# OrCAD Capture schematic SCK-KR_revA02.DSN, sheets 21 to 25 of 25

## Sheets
21 21_PL_GEM3: size Custom
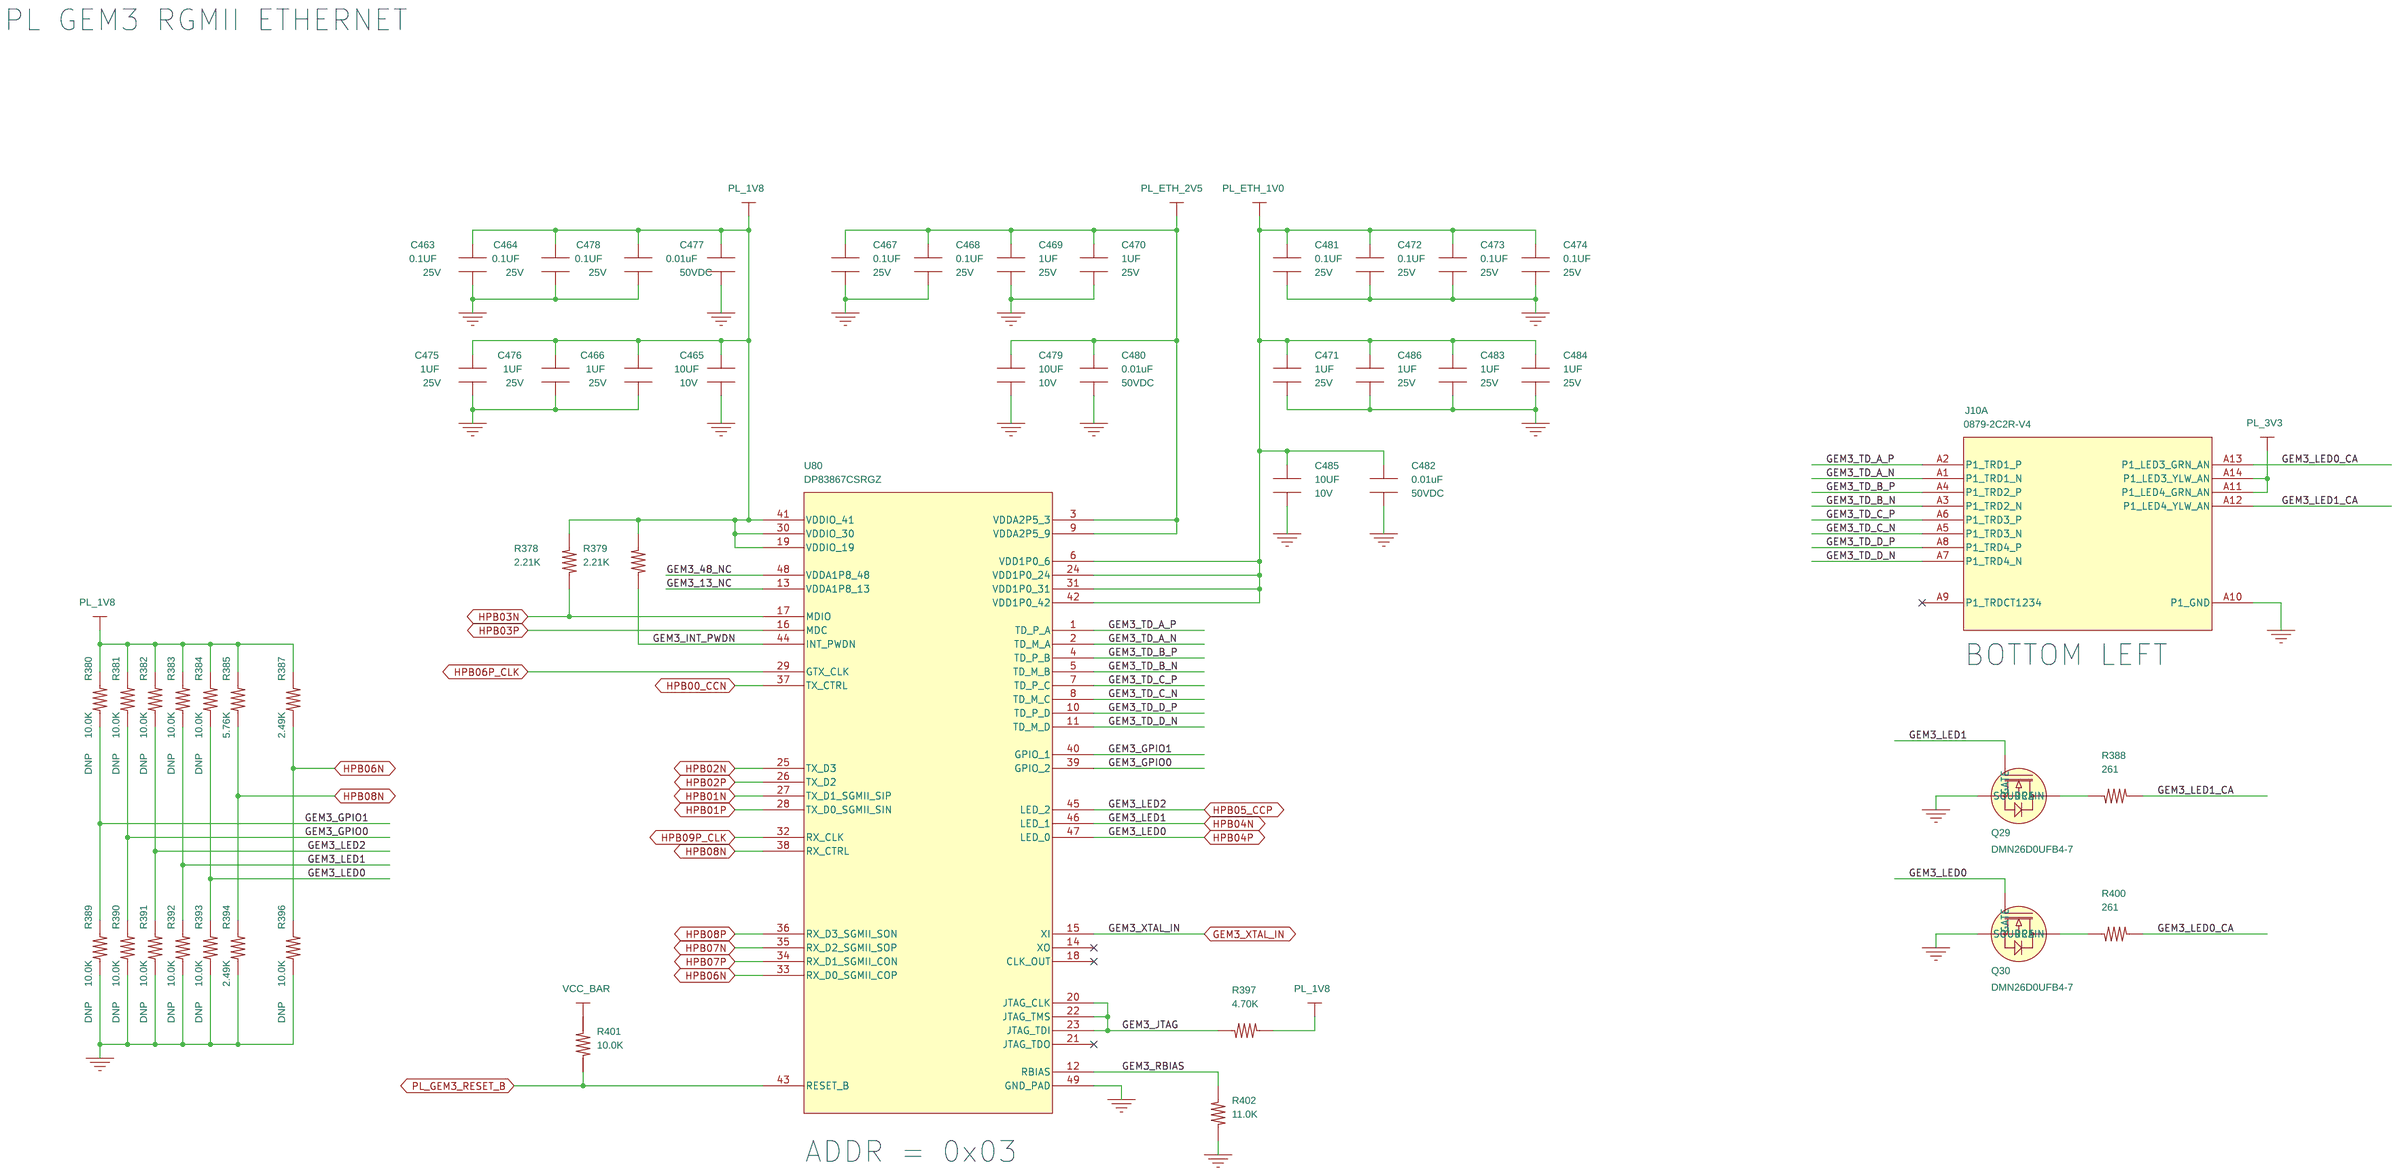
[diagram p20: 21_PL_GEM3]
22 22_SD Card: size Custom
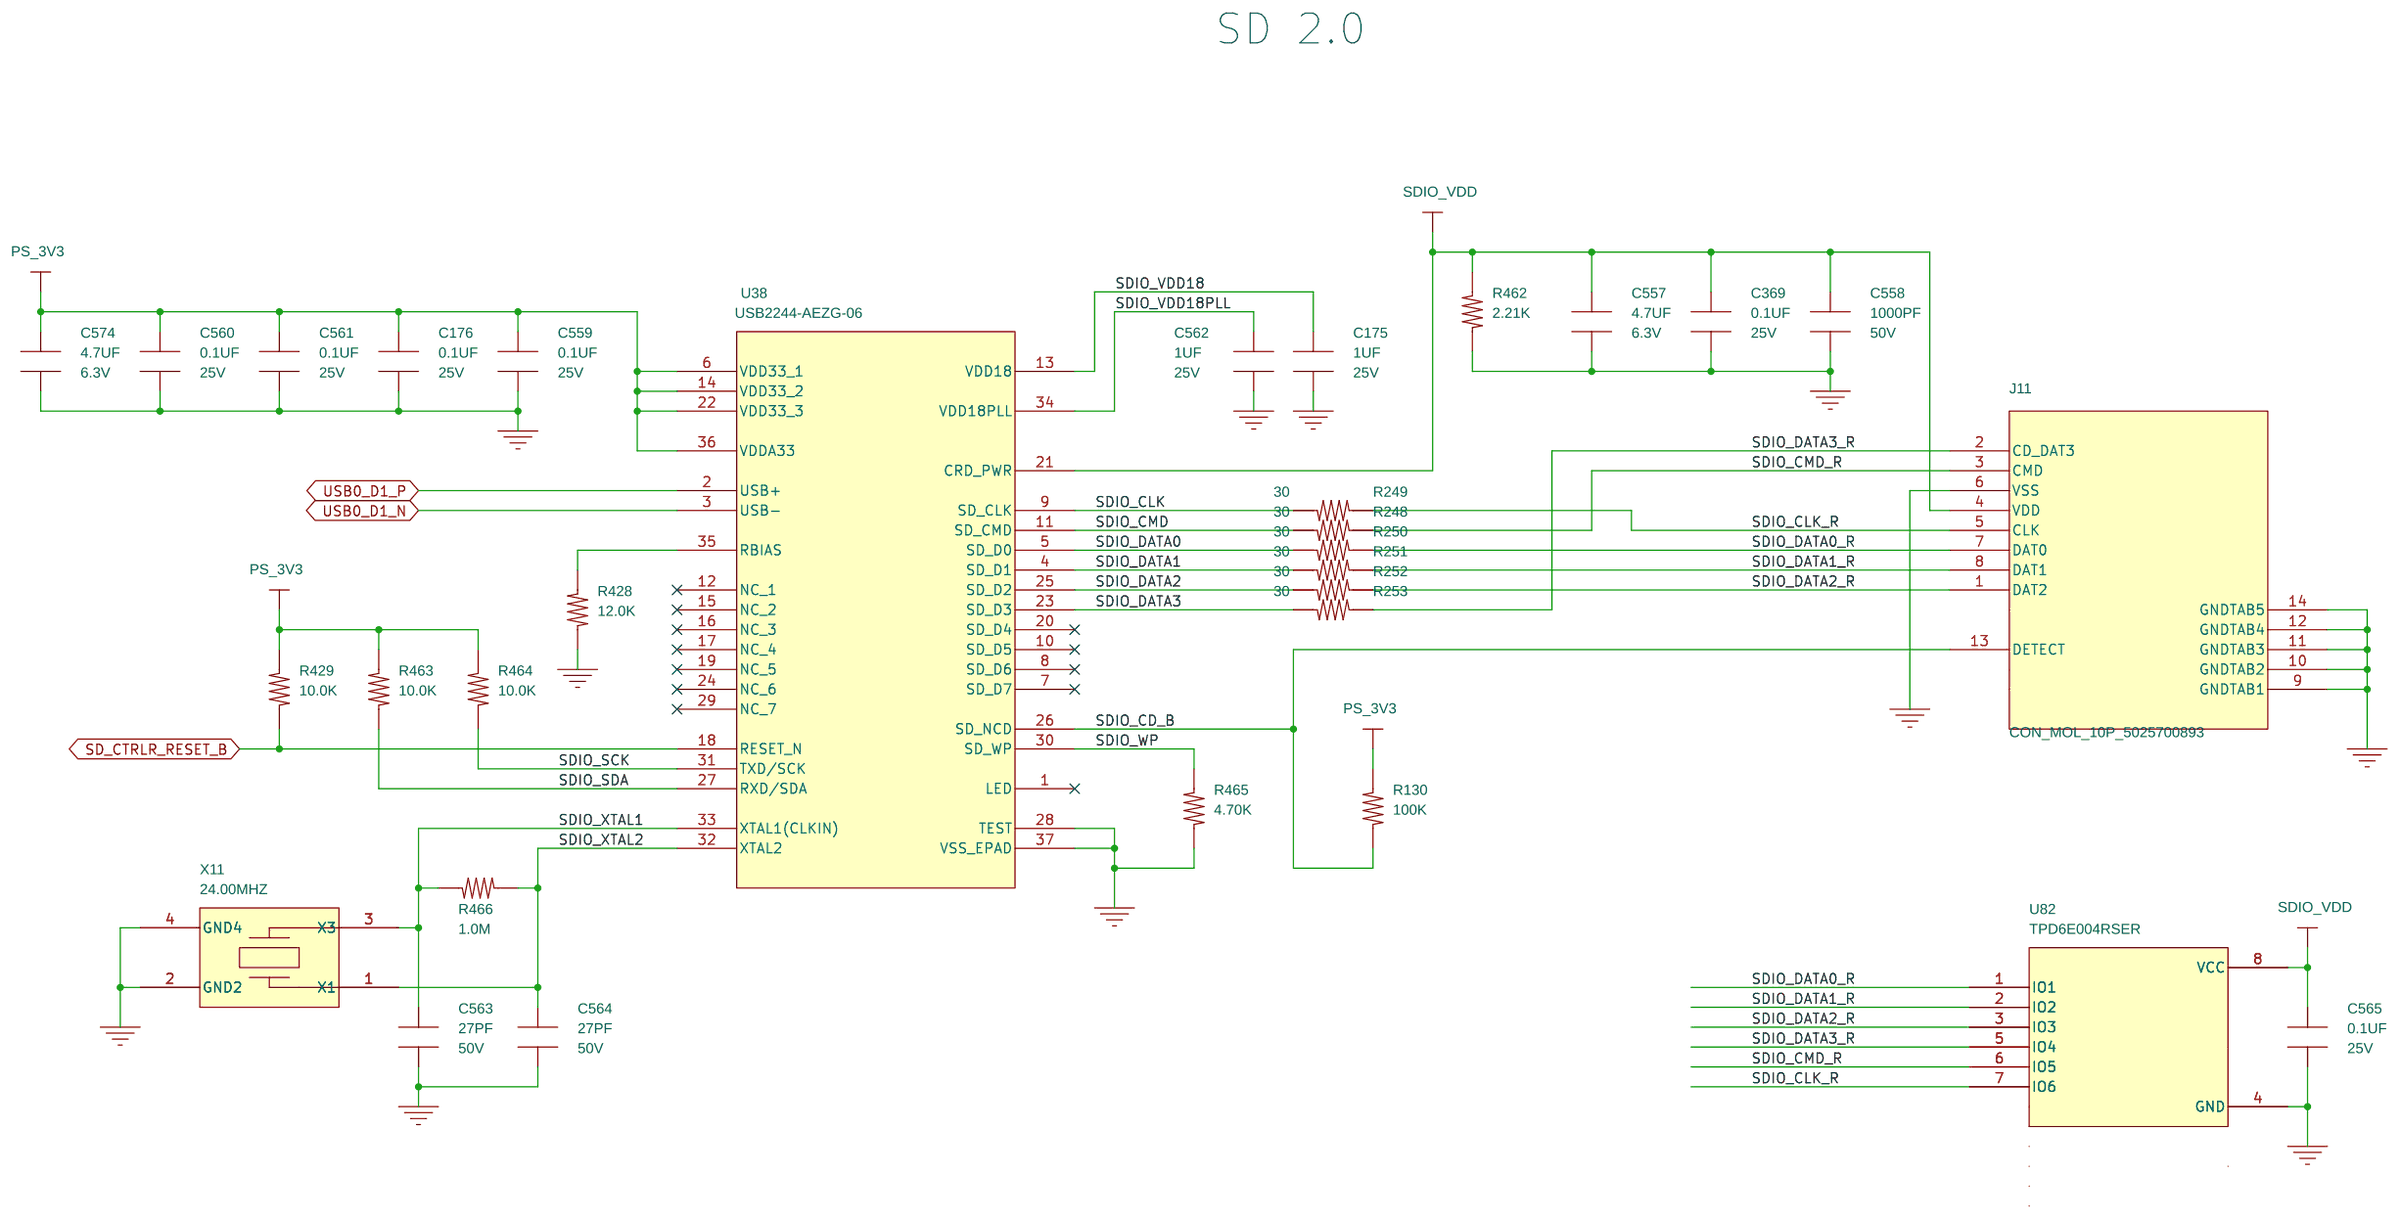
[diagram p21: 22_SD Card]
23 23_USB Connectors: size Custom
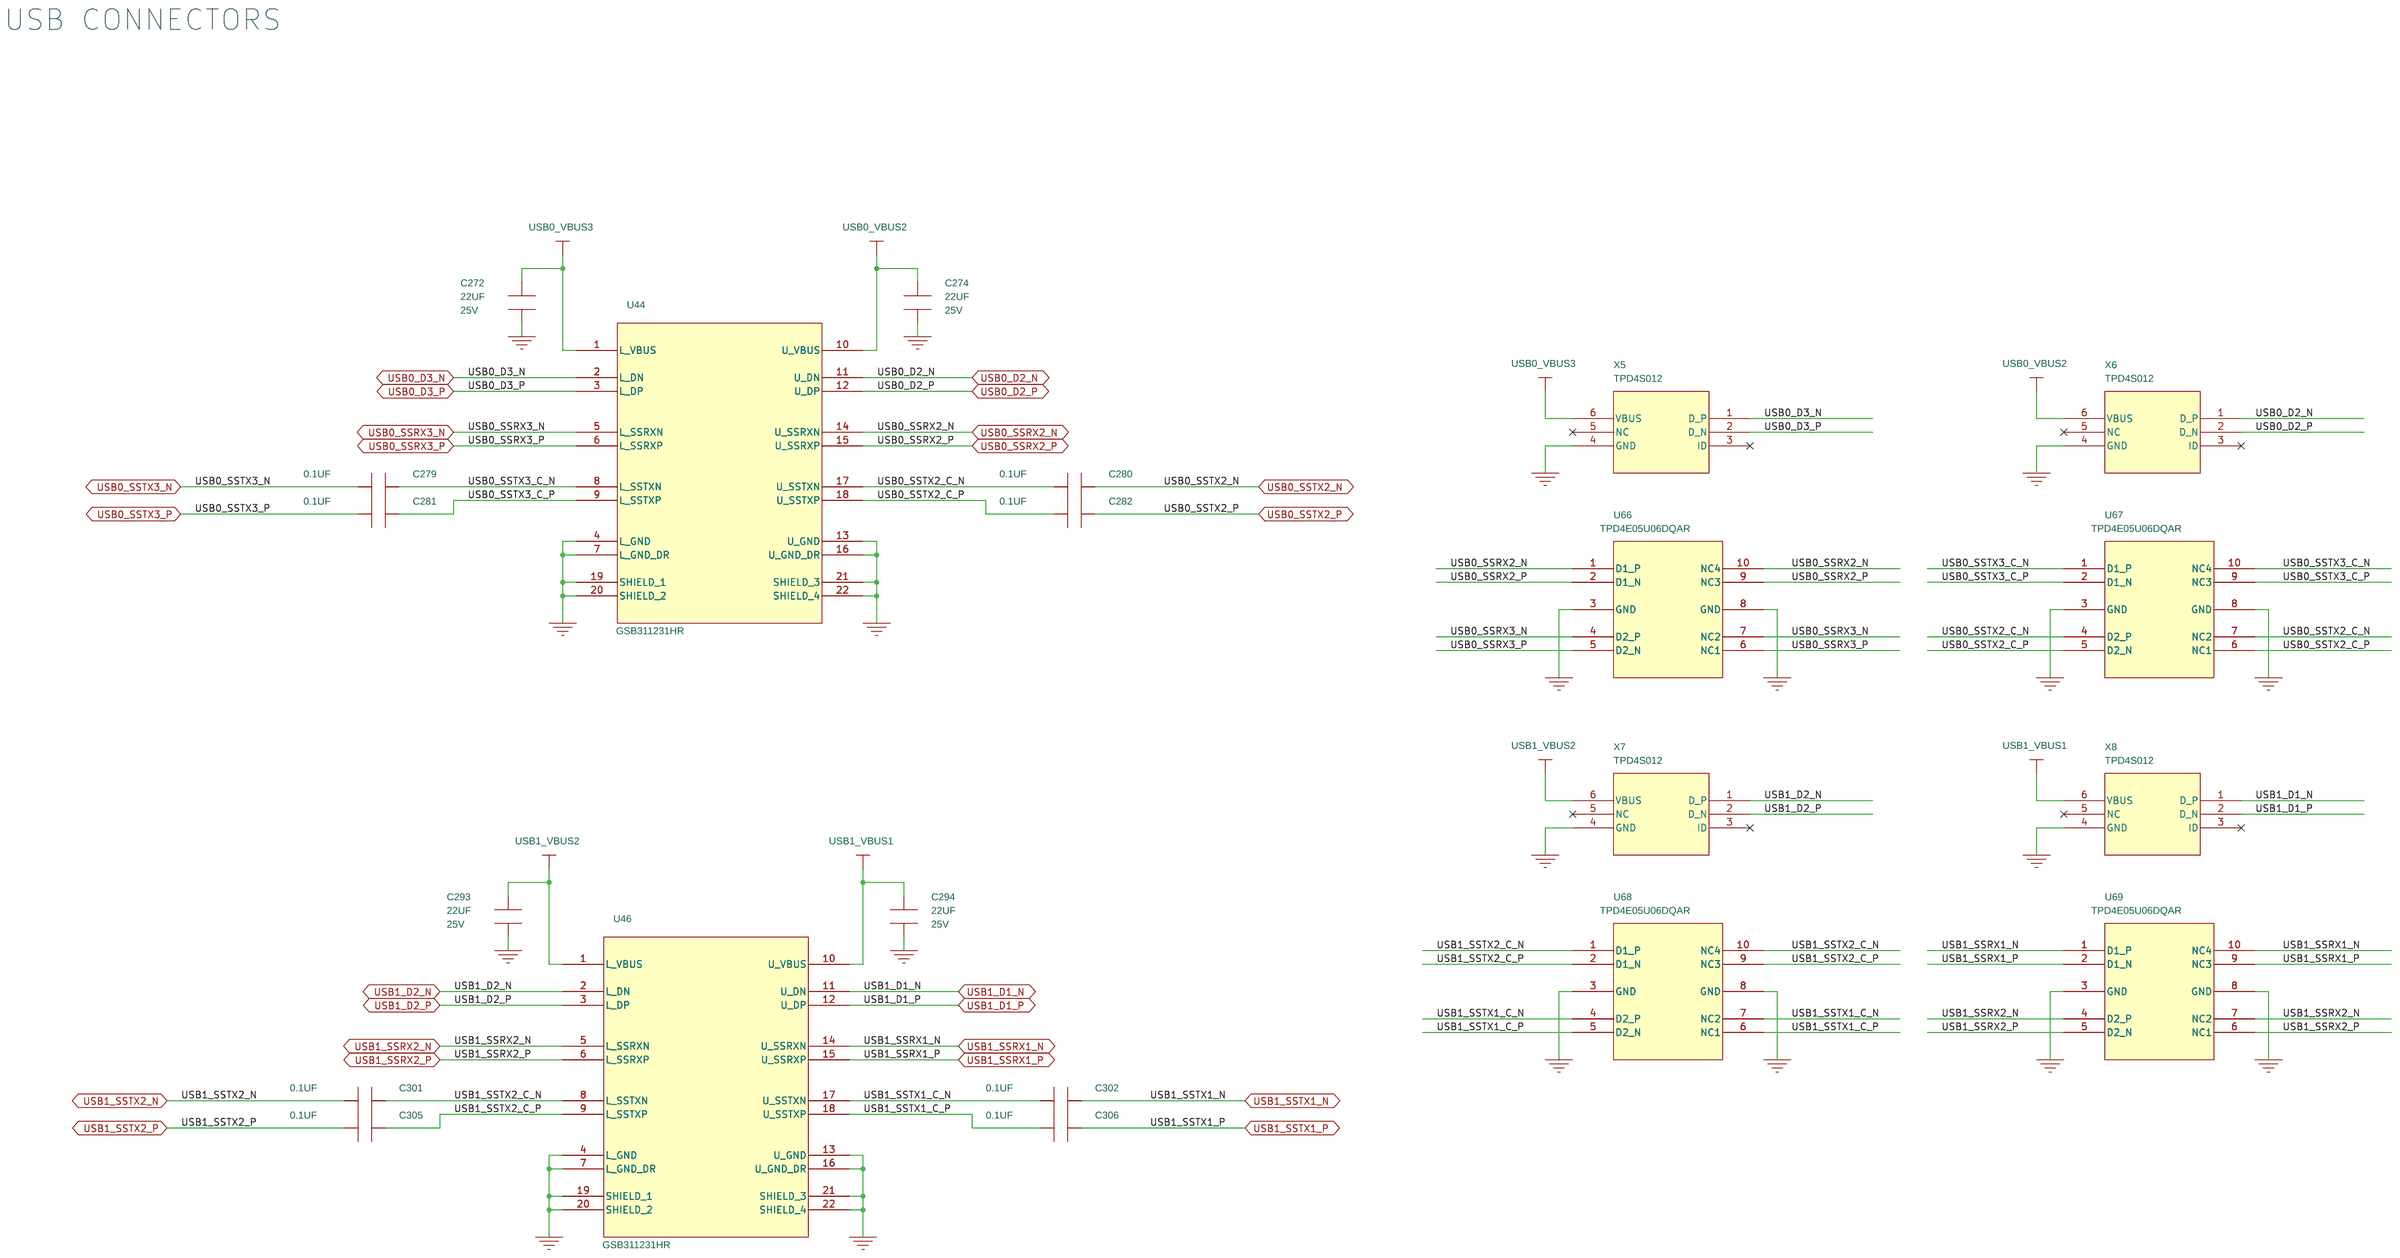
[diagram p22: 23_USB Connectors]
24 24_USB0 PHY and Hub: size Custom
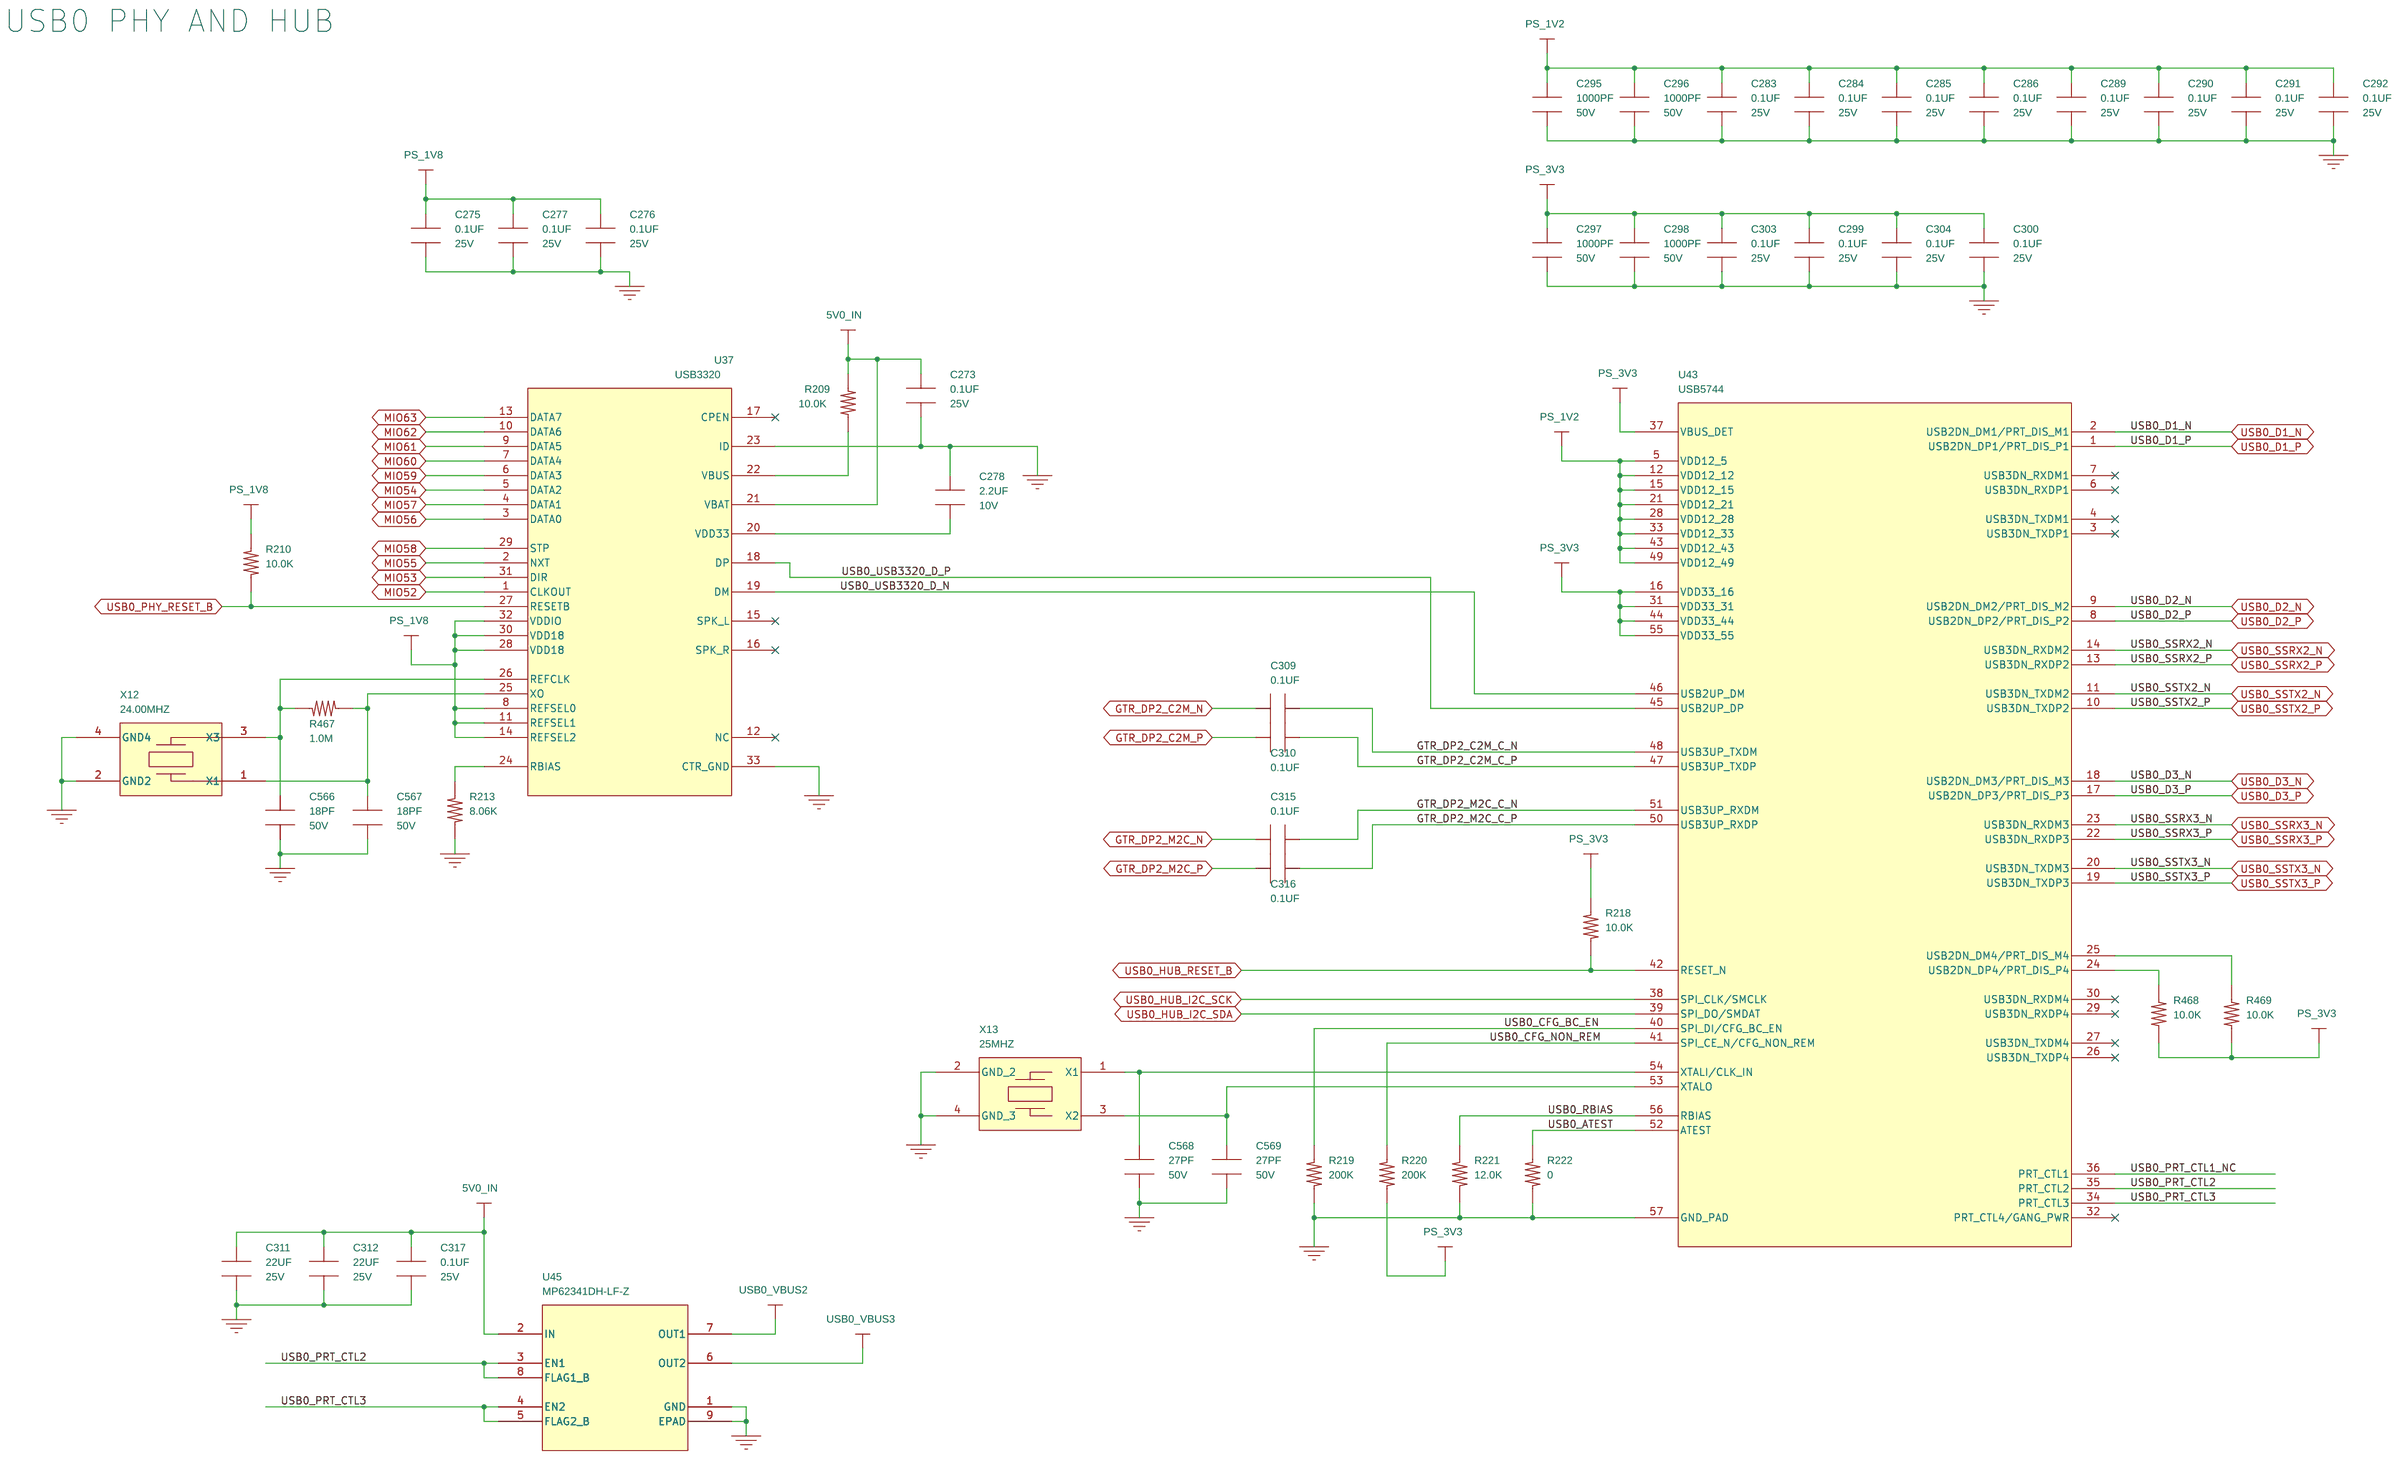
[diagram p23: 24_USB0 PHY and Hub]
25 25_USB1 PHY and Hub: size Custom
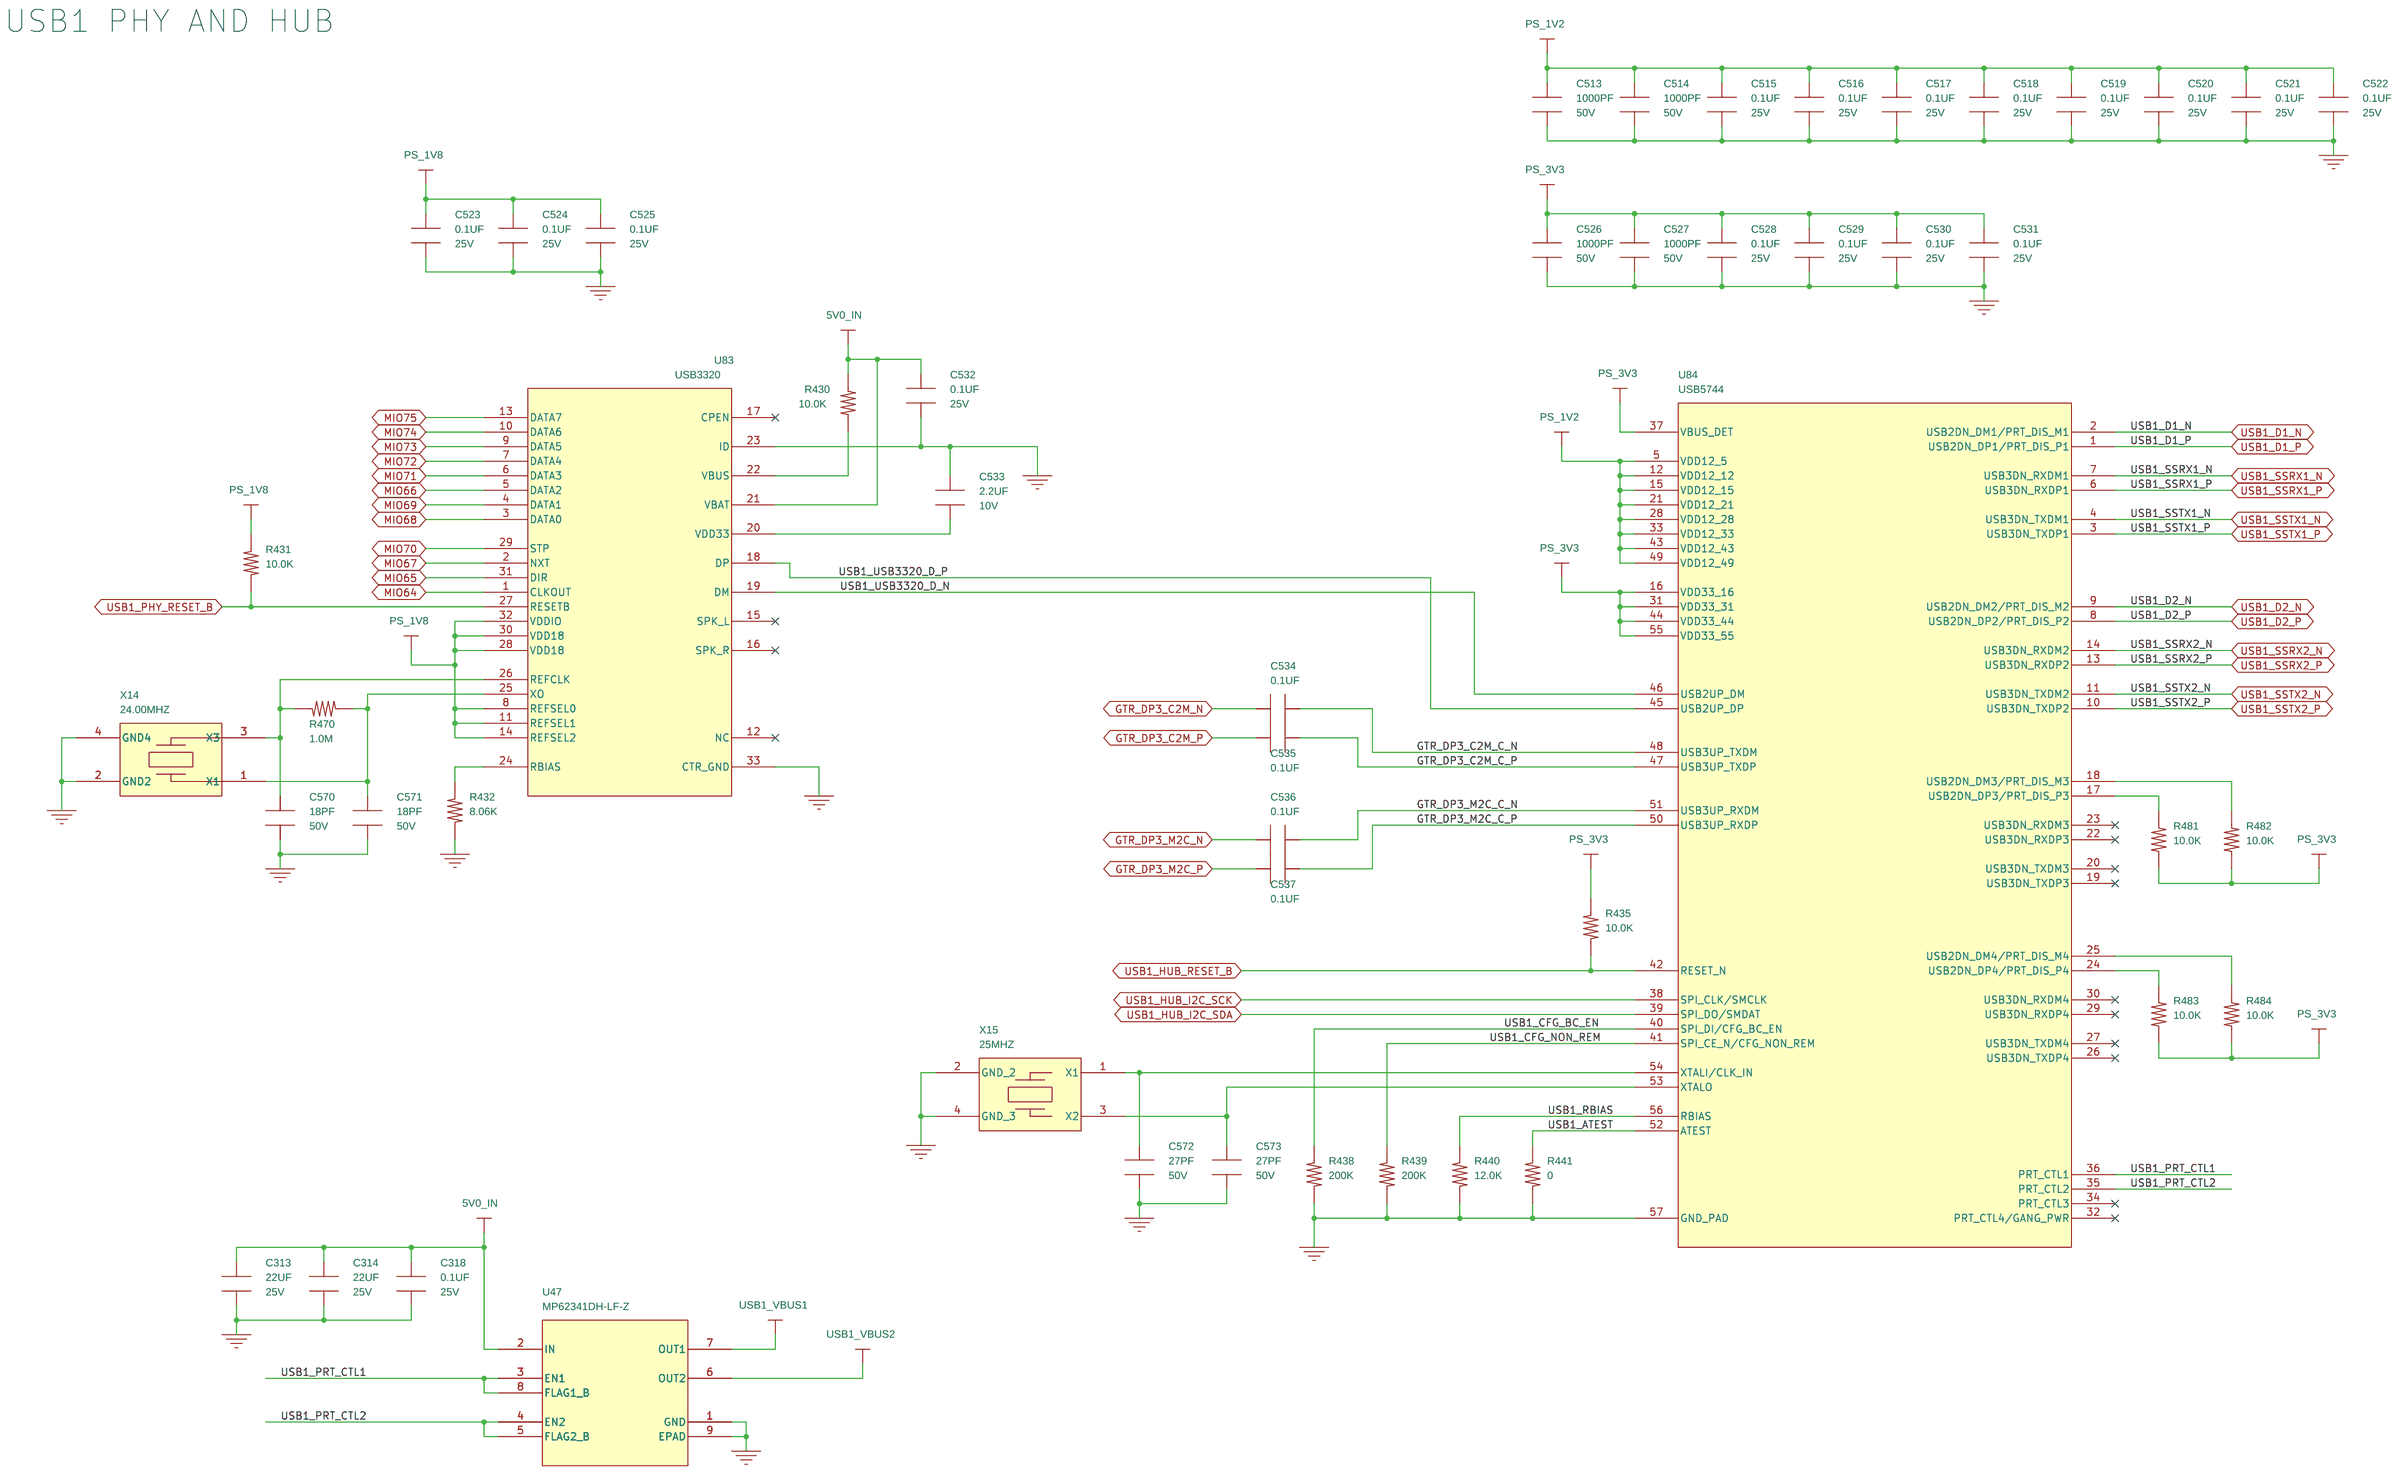
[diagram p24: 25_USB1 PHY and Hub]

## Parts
sheet 18_PS_GEM0
J10  0879-2C2R-V4  [CON_BEL_0879_2C2R_V4]  (sections A,B,C,D)
sheet 21_PL_GEM3
C463  0.1UF  [CAPC100X50X55]
C464  0.1UF  [CAPC100X50X55]
C465  10UF  [CAPC100X50X70]
C466  1UF  [CAPC100X50X70]
C467  0.1UF  [CAPC100X50X55]
C468  0.1UF  [CAPC100X50X55]
C469  1UF  [CAPC100X50X70]
C470  1UF  [CAPC100X50X70]
C471  1UF  [CAPC100X50X70]
C472  0.1UF  [CAPC100X50X55]
C473  0.1UF  [CAPC100X50X55]
C474  0.1UF  [CAPC100X50X55]
C475  1UF  [CAPC100X50X70]
C476  1UF  [CAPC100X50X70]
C477  0.01uF  [CAPC100X50X55]
C478  0.1UF  [CAPC100X50X55]
C479  10UF  [CAPC100X50X70]
C480  0.01uF  [CAPC100X50X55]
C481  0.1UF  [CAPC100X50X55]
C482  0.01uF  [CAPC100X50X55]
C483  1UF  [CAPC100X50X70]
C484  1UF  [CAPC100X50X70]
C485  10UF  [CAPC100X50X70]
C486  1UF  [CAPC100X50X70]
Q29  DMN26D0UFB4-7  [DFN_105X65x40_3]
Q30  DMN26D0UFB4-7  [DFN_105X65x40_3]
R378  2.21K  [RESC100X50X40]
R379  2.21K  [RESC100X50X40]
R380  10.0K  [RESC100X50X40]
R381  10.0K  [RESC100X50X40]
R382  10.0K  [RESC100X50X40]
R383  10.0K  [RESC100X50X40]
R384  10.0K  [RESC100X50X40]
R385  5.76K  [RESC100X50X40]
R387  2.49K  [RESC100X50X40]
R388  261  [RESC100X50X40]
R389  10.0K  [RESC100X50X40]
R390  10.0K  [RESC100X50X40]
R391  10.0K  [RESC100X50X40]
R392  10.0K  [RESC100X50X40]
R393  10.0K  [RESC100X50X40]
R394  2.49K  [RESC100X50X40]
R396  10.0K  [RESC100X50X40]
R397  4.70K  [RESC100X50X40]
R400  261  [RESC100X50X40]
R401  10.0K  [RESC100X50X40]
R402  11.0K  [RESC100X50X40]
U80  DP83867CSRGZ  [VQFN05P700X700X100_48_408EP]
sheet 22_SD Card
C175  1UF  [CAPC100X50X70]
C176  0.1UF  [CAPC100X50X55]
C369  0.1UF  [CAPC100X50X55]
C557  4.7UF  [CAPC100X50X60]
C558  1000PF  [CAPC100X50X55]
C559  0.1UF  [CAPC100X50X55]
C560  0.1UF  [CAPC100X50X55]
C561  0.1UF  [CAPC100X50X55]
C562  1UF  [CAPC100X50X70]
C563  27PF  [CAPC100X50X55]
C564  27PF  [CAPC100X50X55]
C565  0.1UF  [CAPC100X50X55]
C574  4.7UF  [CAPC100X50X60]
J11  CON_MOL_10P_5025700893  [CON_MOL_10P_5025700893]
R130  100K  [RESC100X50X40]
R248  30  [RESC100X50X40]
R249  30  [RESC100X50X40]
R250  30  [RESC100X50X40]
R251  30  [RESC100X50X40]
R252  30  [RESC100X50X40]
R253  30  [RESC100X50X40]
R428  12.0K  [RESC100X50X40]
R429  10.0K  [RESC100X50X40]
R462  2.21K  [RESC100X50X40]
R463  10.0K  [RESC100X50X40]
R464  10.0K  [RESC100X50X40]
R465  4.70K  [RESC100X50X40]
R466  1.0M  [RESC100X50X40]
U38  USB2244-AEZG-06  [QFN05P600X600X85-36_410]
U82  TPD6E004RSER  [uqfn_8]
X11  24.00MHZ  [XTAL_EPSON_FA238]
sheet 23_USB Connectors
C272  22UF  [CAPC200X125X145]
C274  22UF  [CAPC200X125X145]
C279  0.1UF  [CAPC100X50X55]
C280  0.1UF  [CAPC100X50X55]
C281  0.1UF  [CAPC100X50X55]
C282  0.1UF  [CAPC100X50X55]
C293  22UF  [CAPC200X125X145]
C294  22UF  [CAPC200X125X145]
C301  0.1UF  [CAPC100X50X55]
C302  0.1UF  [CAPC100X50X55]
C305  0.1UF  [CAPC100X50X55]
C306  0.1UF  [CAPC100X50X55]
U44  GSB311231HR  [CONN_USB_DUAL_GSB311231HR]
U46  GSB311231HR  [CONN_USB_DUAL_GSB311231HR]
U66  TPD4E05U06DQAR  [DQA_R_PSON_N10]
U67  TPD4E05U06DQAR  [DQA_R_PSON_N10]
U68  TPD4E05U06DQAR  [DQA_R_PSON_N10]
U69  TPD4E05U06DQAR  [DQA_R_PSON_N10]
X5  TPD4S012  [DRY_6_SON]
X6  TPD4S012  [DRY_6_SON]
X7  TPD4S012  [DRY_6_SON]
X8  TPD4S012  [DRY_6_SON]
sheet 24_USB0 PHY and Hub
C273  0.1UF  [CAPC100X50X55]
C275  0.1UF  [CAPC100X50X55]
C276  0.1UF  [CAPC100X50X55]
C277  0.1UF  [CAPC100X50X55]
C278  2.2UF  [CAPC100X50X55]
C283  0.1UF  [CAPC100X50X55]
C284  0.1UF  [CAPC100X50X55]
C285  0.1UF  [CAPC100X50X55]
C286  0.1UF  [CAPC100X50X55]
C289  0.1UF  [CAPC100X50X55]
C290  0.1UF  [CAPC100X50X55]
C291  0.1UF  [CAPC100X50X55]
C292  0.1UF  [CAPC100X50X55]
C295  1000PF  [CAPC100X50X55]
C296  1000PF  [CAPC100X50X55]
C297  1000PF  [CAPC100X50X55]
C298  1000PF  [CAPC100X50X55]
C299  0.1UF  [CAPC100X50X55]
C300  0.1UF  [CAPC100X50X55]
C303  0.1UF  [CAPC100X50X55]
C304  0.1UF  [CAPC100X50X55]
C309  0.1UF  [CAPC100X50X55]
C310  0.1UF  [CAPC100X50X55]
C311  22UF  [CAPC200X125X145]
C312  22UF  [CAPC200X125X145]
C315  0.1UF  [CAPC100X50X55]
C316  0.1UF  [CAPC100X50X55]
C317  0.1UF  [CAPC100X50X55]
C566  18PF  [CAPC100X50X50]
C567  18PF  [CAPC100X50X50]
C568  27PF  [CAPC100X50X55]
C569  27PF  [CAPC100X50X55]
R209  10.0K  [RESC100X50X40]
R210  10.0K  [RESC100X50X40]
R213  8.06K  [RESC100X50X40]
R218  10.0K  [RESC100X50X40]
R219  200K  [RESC100X50X40]
R220  200K  [RESC100X50X40]
R221  12.0K  [RESC100X50X40]
R222  0  [RESC100X50X40]
R467  1.0M  [RESC100X50X40]
R468  10.0K  [RESC100X50X40]
R469  10.0K  [RESC100X50X40]
U37  USB3320  [QFN05P500X500X100_32P_330EP]
U43  USB5744  [VQFN40P700X700X100-56_460EP]
U45  MP62341DH-LF-Z  [MSOP8E65P490X110]
X12  24.00MHZ  [XTAL_EPSON_FA238]
X13  25MHZ  [XTAL_EPSON_FA238]
sheet 25_USB1 PHY and Hub
C313  22UF  [CAPC200X125X145]
C314  22UF  [CAPC200X125X145]
C318  0.1UF  [CAPC100X50X55]
C513  1000PF  [CAPC100X50X55]
C514  1000PF  [CAPC100X50X55]
C515  0.1UF  [CAPC100X50X55]
C516  0.1UF  [CAPC100X50X55]
C517  0.1UF  [CAPC100X50X55]
C518  0.1UF  [CAPC100X50X55]
C519  0.1UF  [CAPC100X50X55]
C520  0.1UF  [CAPC100X50X55]
C521  0.1UF  [CAPC100X50X55]
C522  0.1UF  [CAPC100X50X55]
C523  0.1UF  [CAPC100X50X55]
C524  0.1UF  [CAPC100X50X55]
C525  0.1UF  [CAPC100X50X55]
C526  1000PF  [CAPC100X50X55]
C527  1000PF  [CAPC100X50X55]
C528  0.1UF  [CAPC100X50X55]
C529  0.1UF  [CAPC100X50X55]
C530  0.1UF  [CAPC100X50X55]
C531  0.1UF  [CAPC100X50X55]
C532  0.1UF  [CAPC100X50X55]
C533  2.2UF  [CAPC100X50X55]
C534  0.1UF  [CAPC100X50X55]
C535  0.1UF  [CAPC100X50X55]
C536  0.1UF  [CAPC100X50X55]
C537  0.1UF  [CAPC100X50X55]
C570  18PF  [CAPC100X50X50]
C571  18PF  [CAPC100X50X50]
C572  27PF  [CAPC100X50X55]
C573  27PF  [CAPC100X50X55]
R430  10.0K  [RESC100X50X40]
R431  10.0K  [RESC100X50X40]
R432  8.06K  [RESC100X50X40]
R435  10.0K  [RESC100X50X40]
R438  200K  [RESC100X50X40]
R439  200K  [RESC100X50X40]
R440  12.0K  [RESC100X50X40]
R441  0  [RESC100X50X40]
R470  1.0M  [RESC100X50X40]
R481  10.0K  [RESC100X50X40]
R482  10.0K  [RESC100X50X40]
R483  10.0K  [RESC100X50X40]
R484  10.0K  [RESC100X50X40]
U47  MP62341DH-LF-Z  [MSOP8E65P490X110]
U83  USB3320  [QFN05P500X500X100_32P_330EP]
U84  USB5744  [VQFN40P700X700X100-56_460EP]
X14  24.00MHZ  [XTAL_EPSON_FA238]
X15  25MHZ  [XTAL_EPSON_FA238]

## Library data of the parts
J10 = RJ45_0879-2C2R-V4: Conn Rcpt RJ-45 1000Base-T RA  Quad 2x2 1.27mm P TH 4-LED Y/G Magnetics; Agile Part Number: CON-00474-01; Barcode: 40000147; CIP Link: http://xsjbrdwin1/CIP-E/Component/Index/All?pn=40000147; Part Type: Unassigned Part Type
C176 C273 C275-C277 C279-C286 C289-C292 C299-C306 C309 C310 C315-C318 C369 C463 C464 C467 C468 C472-C474 C478 C481 C515-C525 C528-C532 C534-C537 C559-C561 C565 = CAP_NP: Cap Cer 100nF 10% 25V X5R 0402; ALT_SYMBOLS: CAPC100X50X55RND; Agile Part Number: CAP-00068-01; CIP Link: http://xsjbrdwin1/CIP-E/Component/Index/All?pn=100040; Dielectric Type: X5R; Manufacturer: TAIYO YUDEN; Manufacturer PN: TMK105BJ104KV-F; OWNER: 4001; PRICE: 0.01; Part Type: CERAMIC; PartType: CERAMIC; ROHS: Yes; Tolerance: 10%; Voltage: 25V; barcode: 100040
C465 C479 C485 = CAP_NP: Cap Cer 10uF 20% 10V X5R 0402; Agile Part Number: CAP-00170-01; CIP Link: http://xsjbrdwin1/CIP-E/Component/Index/All?pn=100197; Dielectric Type: X5R; Manufacturer: SAMSUNG; Manufacturer PN: CL05A106MP5NUNC; OWNER: 3709; PRICE: 0.09; Part Type: CERAMIC; PartType: CERAMIC; ROHS: Yes; Tolerance: 20%; Voltage: 10V; barcode: 100197
C175 C466 C469-C471 C475 C476 C483 C484 C486 C562 = CAP_NP: Cap Cer 1uF 10% 25V X6S 0402; ALT_SYMBOLS: CAPC100X50X55RND; Agile Part Number: CAP-00009-01; Barcode: 100269; CIP Link: http://xsjbrdwin1/CIP-E/Component/Index/All?pn=100269; Dielectric Type: X6S; Manufacturer: MURATA; Manufacturer PN: GRM155C81E105KE11D; Part Type: CERAMIC; Tolerance: 10%; Voltage: 25V
C477 C480 C482 = CAP_NP: Cap Cer 10nF 10% 50V X7R 0402; ALT_SYMBOLS: CAPC100X50X55RND; Agile Part Number: CAP-00031-01; CIP Link: http://xsjbrdwin1/CIP-E/Component/Index/All?pn=100003; Dielectric Type: X7R; Manufacturer: Yageo; Manufacturer PN: CC0402KRX7R9BB103; OWNER: 4001; PRICE: 0; Part Type: CERAMIC; PartType: CERAMIC; ROHS: Yes; Tolerance: 10%; Voltage: 50VDC; barcode: 100003; Datasheet: http://download.siliconexpert.com/pdfs/2017/7/31/11/40/26/700/yageo_/manual/1073881636569039upy-gphc_x7r_6.3v-to-50v_18.pdf
Q29 Q30 = DMN26D0UFB4: MOSFET N-CH 20V 230MA DFN; Agile Part Number: TRN-00054-01; Barcode: 83000008; CIP Link: http://xsjbrdwin1/CIP-E/Component/Index/All?pn=83000008; Manufacturer: Diodes Incorporated; Part Type: FET; Rated Power: 350mW (Ta); Datasheet: https://www.diodes.com/assets/Datasheets/ds31775.pdf
R378 R379 R462 = RES: Res 2K21 1% 1/16W 100PPM 50V 0402; ALT_SYMBOLS: (0402,C402-25,RESC100X50X40L25NRND); Agile Part Number: RES-00023-01; Barcode: 200163; CIP Link: http://xsjbrdwin1/CIP-E/Component/Index/All?pn=200163; Manufacturer: PANASONIC; Manufacturer PN: ERJ2RKF2211X; OWNER: 3709; PRICE: 0; Part Type: SMT - 1%; PartType: SMT - 1%; Power: 1/10W; ROHS: Yes; Rated Power: 1/16W; Tolerance: 1%; primarykey: 254
R380-R384 R389-R393 R396 = RES: Res 10K 1% 1/16W 100PPM 50V 0402; ALT_SYMBOLS: RESC100X50X40RND; ASSEMBLY_OPTIONS: DNP; Agile Part Number: RES-00030-01; Barcode: 200025; CIP Link: http://xsjbrdwin1/CIP-E/Component/Index/All?pn=200025; Manufacturer: PANASONIC; Manufacturer PN: ERJ2RKF1002X; OWNER: 3709; PRICE: 0; Part Type: SMT - 1%; PartType: SMT - DNP; Power: DNP; ROHS: Yes; Rated Power: 1/16W; Tolerance: 1%; primarykey: 73
R385 = RES: RES 5.76 KOHM 1% 1/10W 0402; ALT_SYMBOLS: (0402,C402-25,RESC100X50X40L25NRND); Agile Part Number: RES-00179-01; Barcode: 200184; CIP Link: http://xsjbrdwin1/CIP-E/Component/Index/All?pn=200184; Manufacturer: PANASONIC; Manufacturer PN: ERJ-2RKF5761X; OWNER: 3709; PRICE: 0; Part Type: SMT - 1%; PartType: SMT - 1%; Power: 1/10W; ROHS: Yes; Rated Power: 1/10W; Tolerance: 1%; primarykey: 122
R387 R394 = RES: Res 2K49 1% 1/16W 100PPM 50V 0402; Agile Part Number: RES-00085-01; Barcode: 200049; CIP Link: http://xsjbrdwin1/CIP-E/Component/Index/All?pn=200049; Manufacturer: PANASONIC; Manufacturer PN: ERJ2RKF2491X; OWNER: 10460; PRICE: 0; Part Type: SMT - 1%; PartType: SMT - 1%; Power: 1/10W; ROHS: Yes; Rated Power: 1/16W; Tolerance: 1%; primarykey: 161
R388 R400 = RES: Res 261R 1% 1/16W 100PPM 50V 0402; ALT_SYMBOLS: RESC100X50X40RND; Agile Part Number: RES-00086-01; Barcode: 200050; CIP Link: http://xsjbrdwin1/CIP-E/Component/Index/All?pn=200050; Manufacturer: PANASONIC; Manufacturer PN: ERJ2RKF2610X; OWNER: 3501; PRICE: 0; Part Type: SMT - 1%; PartType: SMT - 1%; Power: 1/10W; ROHS: Yes; Rated Power: 1/16W; Tolerance: 1%; primarykey: 60
R397 R465 = RES: Res 4K7 1% 1/16W 100PPM 50V 0402; ALT_SYMBOLS: RESC100X50X40RND; Agile Part Number: RES-00035-01; Barcode: 200067; CIP Link: http://xsjbrdwin1/CIP-E/Component/Index/All?pn=200067; Manufacturer: PANASONIC; Manufacturer PN: ERJ2RKF4701X; OWNER: 3670; PRICE: 0.01; Part Type: SMT - 1%; PartType: SMT - 1%; Power: 1/16W; ROHS: Yes; Rated Power: 1/16W; Tolerance: 1%; primarykey: 128
R401 = RES: Res 10K 1% 1/16W 100PPM 50V 0402; ALT_SYMBOLS: RESC100X50X40RND; Agile Part Number: RES-00030-01; Barcode: 200025; CIP Link: http://xsjbrdwin1/CIP-E/Component/Index/All?pn=200025; Manufacturer: PANASONIC; Manufacturer PN: ERJ2RKF1002X; OWNER: 4001; PRICE: 0; Part Type: SMT - 1%; PartType: SMT - 1%; Power: 1/10W; ROHS: Yes; Rated Power: 1/16W; Tolerance: 1%; primarykey: 1
R402 = RES: Res 11K 1% 1/16W 100PPM 50V 0402; ALT_SYMBOLS: RESC100X50X40RND; Agile Part Number: RES-00268-01; Barcode: 200289; CIP Link: http://xsjbrdwin1/CIP-E/Component/Index/All?pn=200289; Manufacturer: PANASONIC; Manufacturer PN: ERJ2RKF1102X; OWNER: 3501; PRICE: 0; Part Type: SMT - 1%; PartType: SMT - 1%; Power: 1/10W; ROHS: Yes; Rated Power: 1/16W; Tolerance: 1%; primarykey: 156
U80 = DP83867ISRGZ: IC PHY Ethernet Single 10/100/1000 Mbps 1.8-3.3V SGMII/RGMII VQFN-48; Agile Part Number: ICS-00865-01; Barcode: 50000316; CIP Link: http://xsjbrdwin1/CIP-E/Component/Index/All?pn=50000316; Part Type: ETHERNET PHY
C557 C574 = CAP_NP: Cap Cer 4.7uF 20% 6.3V X5R 0402; ALT_SYMBOLS: CAPC100X50X60RND; Agile Part Number: CAP-00085-01; CIP Link: http://xsjbrdwin1/CIP-E/Component/Index/All?pn=100067; Dielectric Type: X5R; Manufacturer: MURATA; Manufacturer PN: GRM155R60J475ME47D; OWNER: 3709; PRICE: 0.06; Part Type: CERAMIC; PartType: CERAMIC; ROHS: Yes; Tolerance: 20%; Voltage: 6.3V; barcode: 100067
C295-C298 C513 C514 C526 C527 C558 = CAP_NP: Cap Cer 1nF 10% 50V X7R 0402; ALT_SYMBOLS: CAPC100X50X55RND; Agile Part Number: CAP-00036-01; Barcode: 100013; CIP Link: http://xsjbrdwin1/CIP-E/Component/Index/All?pn=100013; Dielectric Type: X7R; Manufacturer: MURATA; Manufacturer PN: GCM155R71H102KA37D; Part Type: CERAMIC; Tolerance: 10%; Voltage: 50V
C563 C564 C568 C569 C572 C573 = CAP_NP: Cap Cer 27pF 5% 50V C0G 0402; ALT_SYMBOLS: CAPC100X50X55RND; Agile Part Number: CAP-00037-01; Barcode: 100217; CIP Link: http://xsjbrdwin1/CIP-E/Component/Index/All?pn=100217; Dielectric Type: NP0; Part Type: CERAMIC; Tolerance: 5%; Voltage: 50V
J11 = 5025700893: Conn Rcpt Skt Micro SD Card RA 8 Pos 1x8 1.1mm P Black SMT Push-Push; Agile Part Number: CON-00148-01; Barcode: 400081; CIP Link: http://xsjbrdwin1/CIP-E/Component/Index/All?pn=400081; Manufacturer: MOLEX; OWNER: 3709; PRICE: 2.17; Part Type: SD-SLOT; PartType: SD-SLOT; Pins: 14PINS; Pitch: 1.1MM; ROHS: Yes
R130 = RES: Res 100K 1% 1/16W 100PPM 50V 0402; ALT_SYMBOLS: RESC100X50X40RND; Agile Part Number: RES-00011-01; Barcode: 200026; CIP Link: http://xsjbrdwin1/CIP-E/Component/Index/All?pn=200026; Manufacturer: PANASONIC; Manufacturer PN: ERJ2RKF1003X; Part Type: SMT - 1%; Rated Power: 1/16W; Tolerance: 1%
R248-R253 = RES: Res 30R 1% 1/16W 100PPM 50V 0402; Agile Part Number: RES-00143-01; Barcode: 200133; CIP Link: http://xsjbrdwin1/CIP-E/Component/Index/All?pn=200133; Manufacturer: PANASONIC; Manufacturer PN: ERJ2RKF30R0X; Part Type: SMT - 1%; Rated Power: 1/16W; Tolerance: 1%
R428 = RES: Res 12K 1% 1/16W 100PPM 50V 0402; ALT_SYMBOLS: RESC100X50X40RND; Agile Part Number: RES-00349-01; Barcode: 200386; CIP Link: http://xsjbrdwin1/CIP-E/Component/Index/All?pn=200386; Part Type: SMT - 1%; Rated Power: 1/16W; Tolerance: 1%
R209 R210 R218 R429-R431 R435 R463 R464 R468 R469 R481-R484 = RES: Res 10K 1% 1/16W 100PPM 50V 0402; ALT_SYMBOLS: RESC100X50X40RND; Agile Part Number: RES-00030-01; Barcode: 200025; CIP Link: http://xsjbrdwin1/CIP-E/Component/Index/All?pn=200025; Manufacturer: PANASONIC; Manufacturer PN: ERJ2RKF1002X; Part Type: SMT - 1%; Rated Power: 1/16W; Tolerance: 1%
R466 R467 R470 = RES: Res 1M 5% 1/16W 200PPM 50V 0402; Agile Part Number: RES-00066-01; Barcode: 200013; CIP Link: http://xsjbrdwin1/CIP-E/Component/Index/All?pn=200013; Part Type: SMT - 5%; Rated Power: 1/16W; Tolerance: 5%
U38 = USB2244: IC MEDIA CTRLR USB 2.0 36-QFNE3; Barcode: 50000330; CIP Link: http://xsjbrdwin1/CIP-E/Component/Index/All?pn=50000330; Part Type: Unassigned Part Type; Supply Voltage: 3V ~ 3.6V
U82 = TPD6E004RSER: TVSD 6-Ch 5.5V UQFN-8 8KV Contact Discharge; Agile Part Number: ICS-00585-01; Barcode: 50000100; CIP Link: http://xsjbrdwin1/CIP-E/Component/Index/All?pn=50000100; Part Type: ESD PROTECTOR
X11 X12 X14 = FA-238A_XTAL: Xtal 24MHz 200uW 40R 18pF 62PPM 3225; Agile Part Number: XTL-00052-01; Barcode: 60000034; CIP Link: http://xsjbrdwin1/CIP-E/Component/Index/All?pn=60000034; Part Type: CRYSTAL
C272 C274 C293 C294 C311-C314 = CAP_NP: Cap Cer 22uF 20% 25V X5R 0805; Agile Part Number: CAP-00209-01; Barcode: 100281; CIP Link: http://xsjbrdwin1/CIP-E/Component/Index/All?pn=100281; Dielectric Type: X5R; Manufacturer: MURATA; Manufacturer PN: GRM21BR61E226ME44L; Part Type: CERAMIC; Tolerance: 20%; Voltage: 25V
U44 U46 = GSB311231HR: CONN RCPT USB3.0 A DUAL STACK PCB R/A; Agile Part Number: CON-00389-01; Barcode: 40000098; CIP Link: http://xsjbrdwin1/CIP-E/Component/Index/All?pn=40000098; Manufacturer: Amphenol ICC (Commercial Products); Number of Pins: 22; Part Type: CONNECTOR; Datasheet: https://www.amphenolcanada.com/ProductSearch/pdf/GSB3_BRO.pdf
U66-U69 = TPD4E05U06DQAR: TVS 4-Ch 5.5V 2.5A 40W USON-10 12KV Contact Discharge; Agile Part Number: ICS-00281-01; Barcode: 500416; CIP Link: http://xsjbrdwin1/CIP-E/Component/Index/All?pn=500416; Manufacturer: TEXAS INSTRUMENTS; Part Type: ESD PROTECTOR
X5-X8 = TPD4S012: TVSD 4-Ch 5.5V 3A 60W SON-6 10KV Contact Discharge; Agile Part Number: ICS-00003-01; Barcode: 500251; CIP Link: http://xsjbrdwin1/CIP-E/Component/Index/All?pn=500251; Family: ESD PROTECTOR; Manufacturer: TEXAS INSTRUMENTS; Manufacturer PN: TPD4S012DRYR; OWNER: 3501; PRICE: 0; Part Type: ESD PROTECTOR; PartType: ZENER; Power: 60MW; ROHS: Yes
C278 C533 = CAP_NP: Cap Cer 2.2uF 10% 10V X6S 0402; ALT_SYMBOLS: CAPC100X50X55RND; Agile Part Number: CAP-00123-01; Barcode: 100136; CIP Link: http://xsjbrdwin1/CIP-E/Component/Index/All?pn=100136; Dielectric Type: X6S; Manufacturer: TDK; Manufacturer PN: C1005X6S1A225K050BC; Part Type: CERAMIC; Tolerance: 10%; Voltage: 10V
C566 C567 C570 C571 = CAP_NP: Cap Cer 18pF 2% 50% C0G 0402; ALT_SYMBOLS: CAPC100X50X50RND; Agile Part Number: CAP-00084-01; Barcode: 100065; CIP Link: http://xsjbrdwin1/CIP-E/Component/Index/All?pn=100065; Dielectric Type: NPO; Part Type: CERAMIC; Tolerance: 5%; Voltage: 50V
R213 R432 = RES: Res 8K06 1% 1/16W 100PPM 50V 0402; ALT_SYMBOLS: RESC100X50X40RND; Agile Part Number: RES-00111-01; Barcode: 200083; CIP Link: http://xsjbrdwin1/CIP-E/Component/Index/All?pn=200083; Manufacturer: PANASONIC; Manufacturer PN: ERJ2RKF8061X; Part Type: SMT - 1%; Rated Power: 1/16W; Tolerance: 1%
R219 R220 R438 R439 = RES: Res 200K 1% 1/16W 100PPM 50V 0402; Agile Part Number: RES-00078-01; Barcode: 200041; CIP Link: http://xsjbrdwin1/CIP-E/Component/Index/All?pn=200041; Manufacturer: PANASONIC; Manufacturer PN: ERJ2RKF2003X; Part Type: SMT - 1%; Rated Power: 1/10W; Tolerance: 1%
R221 R440 = RES: Res 12K 1% 1/16W 100PPM 50V 0402; ALT_SYMBOLS: RESC100X50X40RND; Agile Part Number: RES-00349-01; Barcode: 200386; CIP Link: http://xsjbrdwin1/CIP-E/Component/Index/All?pn=200386; Manufacturer: PANASONIC; Manufacturer PN: ERJ2RKF1202X; Part Type: SMT - 1%; Rated Power: 1/16W; Tolerance: 1%
R222 R441 = RES: Res 0R 50mR 1A 0402; ALT_SYMBOLS: RESC100X50X40RND; Agile Part Number: RES-00010-01; Barcode: 200012; CIP Link: http://xsjbrdwin1/CIP-E/Component/Index/All?pn=200012; Manufacturer: PANASONIC; Manufacturer PN: ERJ2GE0R00X; Part Type: SMT - 5%; Tolerance: 5%
U37 U83 = USB3320_QFN32: IC Xcvr USB 2.0 3.3V VQFN-32 ULPI; Agile Part Number: ICS-00089-01; Barcode: 500065; CIP Link: http://xsjbrdwin1/CIP-E/Component/Index/All?pn=500065; Manufacturer: SMSC; Manufacturer PN: USB3320C-EZK-TR; Part Type: USB TRANSCEIVER
U43 U84 = USB5744: IC Prog Hub USB 3.1 4-Port 3.3V VQFN-56; Agile Part Number: ICS-00326-01; Barcode: 500478; CIP Link: http://xsjbrdwin1/CIP-E/Component/Index/All?pn=500478; Manufacturer: MICROCHIP; Manufacturer PN: USB5744T/2G; Part Type: USB HUB
U45 U47 = MP62341DH: IC Switch Power 2-Ch 1A 5.5V 130mR MSOP-8E; Agile Part Number: ICS-00665-01; Barcode: 50000177; CIP Link: http://xsjbrdwin1/CIP-E/Component/Index/All?pn=50000177; Manufacturer: Monolithic Power Systems Inc.; Part Type: LOAD SWITCH; Supply Voltage: Not Required; Datasheet: https://www.monolithicpower.com/pub/media/document/MP62340_MP62341_r0.9.pdf
X13 X15 = FA238: Xtal 25MHz 200uW 60R 18pF 62PPM 3225 SMT; Agile Part Number: XTL-00053-01; Barcode: 60000035; CIP Link: http://xsjbrdwin1/CIP-E/Component/Index/All?pn=60000035; Part Type: CRYSTAL

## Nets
5V0_IN: C273.1 C311.1 C312.1 C313.1 C314.1 C317.1 C318.1 C532.1 R209.1 R430.1 U37.21(VBAT) U45.2(IN) U47.2(IN) U83.21(VBAT) ; also on sheet 3 4 5 12 16
GND: C175.2 C176.2 C272.2 C273.2 C274.2 C275.2 C276.2 C277.2 C278.1 C283.2 C284.2 C285.2 C286.2 C289.2 C290.2 C291.2 C292.2 C293.2 C294.2 C295.2 C296.2 C297.2 C298.2 C299.2 C300.2 C303.2 C304.2 C311.2 C312.2 C313.2 C314.2 C317.2 C318.2 C369.2 C463.2 C464.2 C465.2 C466.2 C467.2 C468.2 C469.2 C470.2 C471.2 C472.2 C473.2 C474.2 C475.2 C476.2 C477.2 C478.2 C479.2 C480.2 C481.2 C482.2 C483.2 C484.2 C485.2 C486.2 C513.2 C514.2 C515.2 C516.2 C517.2 C518.2 C519.2 C520.2 C521.2 C522.2 C523.2 C524.2 C525.2 C526.2 C527.2 C528.2 C529.2 C530.2 C531.2 C532.2 C533.1 C557.2 C558.2 C559.2 C560.2 C561.2 C562.2 C563.2 C564.2 C565.2 C566.2 C567.2 C568.2 C569.2 C570.2 C571.2 C572.2 C573.2 C574.2 J10.A10(P1_GND) J11.6(VSS) J11.9(GNDTAB1) J11.10(GNDTAB2) J11.11(GNDTAB3) J11.12(GNDTAB4) J11.14(GNDTAB5) Q29.2(SOURCE) Q30.2(SOURCE) R213.2 R219.2 R221.2 R222.2 R389.2 R390.2 R391.2 R392.2 R393.2 R394.2 R396.2 R402.2 R428.2 R432.2 R438.2 R439.2 R440.2 R441.2 R462.2 R465.2 U37.23(ID) U37.33(CTR_GND) U38.28(TEST) U38.37(VSS_EPAD) U43.57(GND_PAD) U44.4(L_GND) U44.7(L_GND_DR) U44.13(U_GND) U44.16(U_GND_DR) U44.19(SHIELD_1) U44.20(SHIELD_2) U44.21(SHIELD_3) U44.22(SHIELD_4) U45.1(GND) U45.9(EPAD) U46.4(L_GND) U46.7(L_GND_DR) U46.13(U_GND) U46.16(U_GND_DR) U46.19(SHIELD_1) U46.20(SHIELD_2) U46.21(SHIELD_3) U46.22(SHIELD_4) U47.1(GND) U47.9(EPAD) U66.3(GND) U66.8(GND) U67.3(GND) U67.8(GND) U68.3(GND) U68.8(GND) U69.3(GND) U69.8(GND) U80.49(GND_PAD) U82.4(GND) U83.23(ID) U83.33(CTR_GND) U84.57(GND_PAD) X5.4(GND) X6.4(GND) X7.4(GND) X8.4(GND) X11.2(GND2) X11.4(GND4) X12.2(GND2) X12.4(GND4) X13.2(GND) X13.4(GND_3) X14.2(GND2) X14.4(GND4) X15.2(GND) X15.4(GND_3) ; also on sheet 3 4 5 6 7 8 9 10 11 12 13 14 15 16 17 18 19 20
GEM3_13_NC: U80.13(VDDA1P8)
GEM3_48_NC: U80.48(VDDA1P8)
GEM3_GPIO0: R381.2 R390.1 U80.39(GPIO_2)
GEM3_GPIO1: R380.2 R389.1 U80.40(GPIO_1)
GEM3_INT_PWDN: R379.2 U80.44(INT_PWDN)
GEM3_JTAG: R397.2 U80.20(JTAG_CLK) U80.22(JTAG_TMS) U80.23(JTAG_TDI)
GEM3_LED0_CA: J10.A13(P1_LED3_GRN_AN) R400.2
GEM3_LED1_CA: J10.A12(P1_LED4_YLW_AN) R388.2
GEM3_RBIAS: R402.1 U80.12(RBIAS)
GEM3_TD_A_N: J10.A1(P1_TRD1_N) U80.2(TD_M_A)
GEM3_TD_A_P: J10.A2(P1_TRD1_P) U80.1(TD_P_A)
GEM3_TD_B_N: J10.A3(P1_TRD2_N) U80.5(TD_M_B)
GEM3_TD_B_P: J10.A4(P1_TRD2_P) U80.4(TD_P_B)
GEM3_TD_C_N: J10.A5(P1_TRD3_N) U80.8(TD_M_C)
GEM3_TD_C_P: J10.A6(P1_TRD3_P) U80.7(TD_P_C)
GEM3_TD_D_N: J10.A7(P1_TRD4_N) U80.11(TD_M_D)
GEM3_TD_D_P: J10.A8(P1_TRD4_P) U80.10(TD_P_D)
GEM3_XTAL_IN: U80.15(XI) ; also on sheet 16
GTR_DP2_C2M_C_N: C309.2 U43.48(USB3UP_TXDM)
GTR_DP2_C2M_C_P: C310.2 U43.47(USB3UP_TXDP)
GTR_DP2_C2M_N: C309.1 ; also on sheet 6
GTR_DP2_C2M_P: C310.1 ; also on sheet 6
GTR_DP2_M2C_C_N: C315.2 U43.51(USB3UP_RXDM)
GTR_DP2_M2C_C_P: C316.2 U43.50(USB3UP_RXDP)
GTR_DP2_M2C_N: C315.1 ; also on sheet 6
GTR_DP2_M2C_P: C316.1 ; also on sheet 6
GTR_DP3_C2M_C_N: C534.2 U84.48(USB3UP_TXDM)
GTR_DP3_C2M_C_P: C535.2 U84.47(USB3UP_TXDP)
GTR_DP3_C2M_N: C534.1 ; also on sheet 6
GTR_DP3_C2M_P: C535.1 ; also on sheet 6
GTR_DP3_M2C_C_N: C536.2 U84.51(USB3UP_RXDM)
GTR_DP3_M2C_C_P: C537.2 U84.50(USB3UP_RXDP)
GTR_DP3_M2C_N: C536.1 ; also on sheet 6
GTR_DP3_M2C_P: C537.1 ; also on sheet 6
HPB00_CCN: U80.37(TX_CTRL) ; also on sheet 7
HPB01N: U80.27(TX_D1_SGMII_SIP) ; also on sheet 7
HPB01P: U80.28(TX_D0_SGMII_SIN) ; also on sheet 7
HPB02N: U80.25(TX_D3) ; also on sheet 7
HPB02P: U80.26(TX_D2) ; also on sheet 7
HPB03N: R378.2 U80.17(MDIO) ; also on sheet 7
HPB03P: U80.16(MDC) ; also on sheet 7
HPB04N: Q29.1(GATE) R383.2 R392.1 U80.46(LED_1) ; also on sheet 7
HPB04P: Q30.1(GATE) R384.2 R393.1 U80.47(LED_0) ; also on sheet 7
HPB05_CCP: R382.2 R391.1 U80.45(LED_2) ; also on sheet 7
HPB06N: R387.2 R396.1 U80.33(RX_D0_SGMII_COP) ; also on sheet 7
HPB06P_CLK: U80.29(GTX_CLK) ; also on sheet 7
HPB07N: U80.35(RX_D2_SGMII_SOP) ; also on sheet 7
HPB07P: U80.34(RX_D1_SGMII_CON) ; also on sheet 7
HPB08N: R385.2 R394.1 U80.38(RX_CTRL) ; also on sheet 7
HPB08P: U80.36(RX_D3_SGMII_SON) ; also on sheet 7
HPB09P_CLK: U80.32(RX_CLK) ; also on sheet 7
MIO52: U37.1(CLKOUT) ; also on sheet 6
MIO53: U37.31(DIR) ; also on sheet 6
MIO54: U37.5(DATA2) ; also on sheet 6
MIO55: U37.2(NXT) ; also on sheet 6
MIO56: U37.3(DATA0) ; also on sheet 6
MIO57: U37.4(DATA1) ; also on sheet 6
MIO58: U37.29(STP) ; also on sheet 6
MIO59: U37.6(DATA3) ; also on sheet 6
MIO60: U37.7(DATA4) ; also on sheet 6
MIO61: U37.9(DATA5) ; also on sheet 6
MIO62: U37.10(DATA6) ; also on sheet 6
MIO63: U37.13(DATA7) ; also on sheet 6
MIO64: U83.1(CLKOUT) ; also on sheet 6
MIO65: U83.31(DIR) ; also on sheet 6
MIO66: U83.5(DATA2) ; also on sheet 6
MIO67: U83.2(NXT) ; also on sheet 6
MIO68: U83.3(DATA0) ; also on sheet 6
MIO69: U83.4(DATA1) ; also on sheet 6
MIO70: U83.29(STP) ; also on sheet 6
MIO71: U83.6(DATA3) ; also on sheet 6
MIO72: U83.7(DATA4) ; also on sheet 6
MIO73: U83.9(DATA5) ; also on sheet 6
MIO74: U83.10(DATA6) ; also on sheet 6
MIO75: U83.13(DATA7) ; also on sheet 6
PL_1V8: C463.1 C464.1 C465.1 C466.1 C475.1 C476.1 C477.1 C478.1 R378.1 R379.1 R380.1 R381.1 R382.1 R383.1 R384.1 R385.1 R387.1 R397.1 R401.1 U80.19(VDDIO) U80.30(VDDIO) U80.41(VDDIO) ; also on sheet 5 6 7 13 16 20
PL_3V3: J10.A11(P1_LED4_GRN_AN) J10.A14(P1_LED3_YLW_AN) ; also on sheet 5 6 7 10 12 14 15 16 20
PL_ETH_1V0: C471.1 C472.1 C473.1 C474.1 C481.1 C482.1 C483.1 C484.1 C485.1 C486.1 U80.6(VDD1P0) U80.24(VDD1P0) U80.31(VDD1P0) U80.42(VDD1P0) ; also on sheet 5 20
PL_ETH_2V5: C467.1 C468.1 C469.1 C470.1 C479.1 C480.1 U80.3(VDDA2P5) U80.9(VDDA2P5) ; also on sheet 5 20
PL_GEM3_RESET_B: R401.2 U80.43(RESET_B) ; also on sheet 16
PS_1V2: C283.1 C284.1 C285.1 C286.1 C289.1 C290.1 C291.1 C292.1 C295.1 C296.1 C513.1 C514.1 C515.1 C516.1 C517.1 C518.1 C519.1 C520.1 C521.1 C522.1 U43.5(VDD12) U43.12(VDD12) U43.15(VDD12) U43.21(VDD12) U43.28(VDD12) U43.33(VDD12) U43.43(VDD12) U43.49(VDD12) U84.5(VDD12) U84.12(VDD12) U84.15(VDD12) U84.21(VDD12) U84.28(VDD12) U84.33(VDD12) U84.43(VDD12) U84.49(VDD12) ; also on sheet 4
PS_1V8: C275.1 C276.1 C277.1 C523.1 C524.1 C525.1 R210.1 R431.1 U37.8(REFSEL0) U37.11(REFSEL1) U37.14(REFSEL2) U37.28(VDD18) U37.30(VDD18) U37.32(VDDIO) U83.8(REFSEL0) U83.11(REFSEL1) U83.14(REFSEL2) U83.28(VDD18) U83.30(VDD18) U83.32(VDDIO) ; also on sheet 4 8 9 15 16 17 18 19
PS_3V3: C176.1 C297.1 C298.1 C299.1 C300.1 C303.1 C304.1 C526.1 C527.1 C528.1 C529.1 C530.1 C531.1 C559.1 C560.1 C561.1 C574.1 R130.1 R218.1 R220.2 R429.1 R435.1 R463.1 R464.1 R468.2 R469.2 R481.2 R482.2 R483.2 R484.2 U38.6(VDD33_1) U38.14(VDD33_2) U38.22(VDD33_3) U38.36(VDDA33) U43.16(VDD33) U43.31(VDD33) U43.37(VBUS_DET) U43.44(VDD33) U43.55(VDD33) U84.16(VDD33) U84.31(VDD33) U84.37(VBUS_DET) U84.44(VDD33) U84.55(VDD33) ; also on sheet 4 15 16 17 18 19
SD_CTRLR_RESET_B: R429.2 U38.18(RESET_N) ; also on sheet 16
SDIO_CD_B: J11.13(DETECT) R130.2 U38.26(SD_NCD)
SDIO_CLK: R249.1 U38.9(SD_CLK)
SDIO_CLK_R: J11.5(CLK) R249.2 U82.7(IO6)
SDIO_CMD: R248.1 U38.11(SD_CMD)
SDIO_CMD_R: J11.3(CMD) R248.2 U82.6(IO5)
SDIO_DATA0: R250.1 U38.5(SD_D0)
SDIO_DATA0_R: J11.7(DAT0) R250.2 U82.1(IO1)
SDIO_DATA1: R251.1 U38.4(SD_D1)
SDIO_DATA1_R: J11.8(DAT1) R251.2 U82.2(IO2)
SDIO_DATA2: R252.1 U38.25(SD_D2)
SDIO_DATA2_R: J11.1(DAT2) R252.2 U82.3(IO3)
SDIO_DATA3: R253.1 U38.23(SD_D3)
SDIO_DATA3_R: J11.2(CD_DAT3) R253.2 U82.5(IO4)
SDIO_SCK: R464.2 U38.31(TXD/SCK)
SDIO_SDA: R463.2 U38.27(RXD/SDA)
SDIO_VDD: C369.1 C557.1 C558.1 C565.1 J11.4(VDD) R462.1 U38.21(CRD_PWR) U82.8(VCC)
SDIO_VDD18: C175.1 U38.13(VDD18)
SDIO_VDD18PLL: C562.1 U38.34(VDD18PLL)
SDIO_WP: R465.1 U38.30(SD_WP)
SDIO_XTAL1: C563.1 R466.1 U38.33(XTAL1(CLKIN)) X11.3(X3)
SDIO_XTAL2: C564.1 R466.2 U38.32(XTAL2) X11.1(X1)
USB0_ATEST: R222.1 U43.52(ATEST)
USB0_CFG_BC_EN: R219.1 U43.40(SPI_DI/CFG_BC_EN)
USB0_CFG_NON_REM: R220.1 U43.41(SPI_CE_N/CFG_NON_REM)
USB0_D1_N: U38.3(USB-) U43.2(USB2DN_DM1/PRT_DIS_M1)
USB0_D1_P: U38.2(USB+) U43.1(USB2DN_DP1/PRT_DIS_P1)
USB0_D2_N: U43.9(USB2DN_DM2/PRT_DIS_M2) U44.11(U_DN) X6.1(D_P)
USB0_D2_P: U43.8(USB2DN_DP2/PRT_DIS_P2) U44.12(U_DP) X6.2(D_N)
USB0_D3_N: U43.18(USB2DN_DM3/PRT_DIS_M3) U44.2(L_DN) X5.1(D_P)
USB0_D3_P: U43.17(USB2DN_DP3/PRT_DIS_P3) U44.3(L_DP) X5.2(D_N)
USB0_HUB_I2C_SCK: U43.38(SPI_CLK/SMCLK) ; also on sheet 15
USB0_HUB_I2C_SDA: U43.39(SPI_DO/SMDAT) ; also on sheet 15
USB0_HUB_RESET_B: R218.2 U43.42(RESET_N) ; also on sheet 16
USB0_PHY_RESET_B: R210.2 U37.27(RESETB) ; also on sheet 16
USB0_PRT_CTL1_NC: U43.36(PRT_CTL1)
USB0_PRT_CTL2: U43.35(PRT_CTL2) U45.3(EN1) U45.8(FLAG1_B)
USB0_PRT_CTL3: U43.34(PRT_CTL3) U45.4(EN2) U45.5(FLAG2_B)
USB0_RBIAS: R221.1 U43.56(RBIAS)
USB0_SSRX2_N: U43.14(USB3DN_RXDM2) U44.14(U_SSRXN) U66.1(D1_P) U66.10(NC4)
USB0_SSRX2_P: U43.13(USB3DN_RXDP2) U44.15(U_SSRXP) U66.2(D1_N) U66.9(NC3)
USB0_SSRX3_N: U43.23(USB3DN_RXDM3) U44.5(L_SSRXN) U66.4(D2_P) U66.7(NC2)
USB0_SSRX3_P: U43.22(USB3DN_RXDP3) U44.6(L_SSRXP) U66.5(D2_N) U66.6(NC1)
USB0_SSTX2_C_N: C280.1 U44.17(U_SSTXN) U67.4(D2_P) U67.7(NC2)
USB0_SSTX2_C_P: C282.1 U44.18(U_SSTXP) U67.5(D2_N) U67.6(NC1)
USB0_SSTX2_N: C280.2 U43.11(USB3DN_TXDM2)
USB0_SSTX2_P: C282.2 U43.10(USB3DN_TXDP2)
USB0_SSTX3_C_N: C279.2 U44.8(L_SSTXN) U67.1(D1_P) U67.10(NC4)
USB0_SSTX3_C_P: C281.2 U44.9(L_SSTXP) U67.2(D1_N) U67.9(NC3)
USB0_SSTX3_N: C279.1 U43.20(USB3DN_TXDM3)
USB0_SSTX3_P: C281.1 U43.19(USB3DN_TXDP3)
USB0_USB3320_D_N: U37.19(DM) U43.46(USB2UP_DM)
USB0_USB3320_D_P: U37.18(DP) U43.45(USB2UP_DP)
USB0_VBUS2: C274.1 U44.10(U_VBUS) U45.7(OUT1) X6.6(VBUS)
USB0_VBUS3: C272.1 U44.1(L_VBUS) U45.6(OUT2) X5.6(VBUS)
USB1_ATEST: R441.1 U84.52(ATEST)
USB1_CFG_BC_EN: R438.1 U84.40(SPI_DI/CFG_BC_EN)
USB1_CFG_NON_REM: R439.1 U84.41(SPI_CE_N/CFG_NON_REM)
USB1_D1_N: U46.11(U_DN) U84.2(USB2DN_DM1/PRT_DIS_M1) X8.1(D_P)
USB1_D1_P: U46.12(U_DP) U84.1(USB2DN_DP1/PRT_DIS_P1) X8.2(D_N)
USB1_D2_N: U46.2(L_DN) U84.9(USB2DN_DM2/PRT_DIS_M2) X7.1(D_P)
USB1_D2_P: U46.3(L_DP) U84.8(USB2DN_DP2/PRT_DIS_P2) X7.2(D_N)
USB1_HUB_I2C_SCK: U84.38(SPI_CLK/SMCLK) ; also on sheet 15
USB1_HUB_I2C_SDA: U84.39(SPI_DO/SMDAT) ; also on sheet 15
USB1_HUB_RESET_B: R435.2 U84.42(RESET_N) ; also on sheet 16
USB1_PHY_RESET_B: R431.2 U83.27(RESETB) ; also on sheet 16
USB1_PRT_CTL1: U47.3(EN1) U47.8(FLAG1_B) U84.36(PRT_CTL1)
USB1_PRT_CTL2: U47.4(EN2) U47.5(FLAG2_B) U84.35(PRT_CTL2)
USB1_RBIAS: R440.1 U84.56(RBIAS)
USB1_SSRX1_N: U46.14(U_SSRXN) U69.1(D1_P) U69.10(NC4) U84.7(USB3DN_RXDM1)
USB1_SSRX1_P: U46.15(U_SSRXP) U69.2(D1_N) U69.9(NC3) U84.6(USB3DN_RXDP1)
USB1_SSRX2_N: U46.5(L_SSRXN) U69.4(D2_P) U69.7(NC2) U84.14(USB3DN_RXDM2)
USB1_SSRX2_P: U46.6(L_SSRXP) U69.5(D2_N) U69.6(NC1) U84.13(USB3DN_RXDP2)
USB1_SSTX1_C_N: C302.1 U46.17(U_SSTXN) U68.4(D2_P) U68.7(NC2)
USB1_SSTX1_C_P: C306.1 U46.18(U_SSTXP) U68.5(D2_N) U68.6(NC1)
USB1_SSTX1_N: C302.2 U84.4(USB3DN_TXDM1)
USB1_SSTX1_P: C306.2 U84.3(USB3DN_TXDP1)
USB1_SSTX2_C_N: C301.2 U46.8(L_SSTXN) U68.1(D1_P) U68.10(NC4)
USB1_SSTX2_C_P: C305.2 U46.9(L_SSTXP) U68.2(D1_N) U68.9(NC3)
USB1_SSTX2_N: C301.1 U84.11(USB3DN_TXDM2)
USB1_SSTX2_P: C305.1 U84.10(USB3DN_TXDP2)
USB1_USB3320_D_N: U83.19(DM) U84.46(USB2UP_DM)
USB1_USB3320_D_P: U83.18(DP) U84.45(USB2UP_DP)
USB1_VBUS1: C294.1 U46.10(U_VBUS) U47.7(OUT1) X8.6(VBUS)
USB1_VBUS2: C293.1 U46.1(L_VBUS) U47.6(OUT2) X7.6(VBUS)
N3548094: R428.1 U38.35(RBIAS)
N3921502: Q29.3(DRAIN) R388.1
N3921550: Q30.3(DRAIN) R400.1
N3957555: R213.1 U37.24(RBIAS)
N3957585: R209.2 U37.22(VBUS)
N3957595: C278.2 U37.20(VDD33)
N3957977: C568.1 U43.54(XTALI/CLK_IN) X13.1(X1)
N3957979: C569.1 U43.53(XTALO) X13.3(X2)
N3958007: R468.1 U43.24(USB2DN_DP4/PRT_DIS_P4)
N3958011: R469.1 U43.25(USB2DN_DM4/PRT_DIS_M4)
N3958031: C566.1 R467.1 U37.26(REFCLK) X12.3(X3)
N3958033: C567.1 R467.2 U37.25(XO) X12.1(X1)
N3960985: R430.2 U83.22(VBUS)
N3961045: C533.2 U83.20(VDD33)
N3961137: C570.1 R470.1 U83.26(REFCLK) X14.3(X3)
N3961171: R432.1 U83.24(RBIAS)
N3961219: C572.1 U84.54(XTALI/CLK_IN) X15.1(X1)
N3961321: C573.1 U84.53(XTALO) X15.3(X2)
N3961343: C571.1 R470.2 U83.25(XO) X14.1(X1)
N3964179: R482.1 U84.18(USB2DN_DM3/PRT_DIS_M3)
N3964187: R481.1 U84.17(USB2DN_DP3/PRT_DIS_P3)
N3964408: R484.1 U84.25(USB2DN_DM4/PRT_DIS_M4)
N3964416: R483.1 U84.24(USB2DN_DP4/PRT_DIS_P4)

Not connected (* = marked no-connect by the designer): J10 A9(P1_TRDCT1234)*; U37 12(NC)* 15(SPK_L)* 16(SPK_R)* 17(CPEN)*; U38 1(LED)* 7(SD_D7)* 8(SD_D6)* 10(SD_D5)* 12(NC_1)* 15(NC_2)* 16(NC_3)* 17(NC_4)* 19(NC_5)* 20(SD_D4)* 24(NC_6)* 29(NC_7)*; U43 3(USB3DN_TXDP1)* 4(USB3DN_TXDM1)* 6(USB3DN_RXDP1)* 7(USB3DN_RXDM1)* 26(USB3DN_TXDP4)* 27(USB3DN_TXDM4)* 29(USB3DN_RXDP4)* 30(USB3DN_RXDM4)* 32(PRT_CTL4/GANG_PWR)*; U80 14(XO)* 18(CLK_OUT)* 21(JTAG_TDO)*; U83 12(NC)* 15(SPK_L)* 16(SPK_R)* 17(CPEN)*; U84 19(USB3DN_TXDP3)* 20(USB3DN_TXDM3)* 22(USB3DN_RXDP3)* 23(USB3DN_RXDM3)* 26(USB3DN_TXDP4)* 27(USB3DN_TXDM4)* 29(USB3DN_RXDP4)* 30(USB3DN_RXDM4)* 32(PRT_CTL4/GANG_PWR)* 34(PRT_CTL3)*; X5 3(ID)* 5(NC)*; X6 3(ID)* 5(NC)*; X7 3(ID)* 5(NC)*; X8 3(ID)* 5(NC)*

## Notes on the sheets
sheet 21
- PL GEM3 RGMII ETHERNET
- BOTTOM LEFT
- ADDR = 0x03
sheet 22
- SD 2.0
sheet 23
- USB CONNECTORS
sheet 24
- USB0 PHY AND HUB
sheet 25
- USB1 PHY AND HUB
